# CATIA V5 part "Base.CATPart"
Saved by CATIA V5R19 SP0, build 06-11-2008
Part number: Base
Bounding box of the stored display mesh (mm): x -24 to 24, y 0 to 90, z 0 to 54
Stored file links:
  C:\Users\CADCIM\Desktop\CAT19\c13\Excercise-1\Part & Asm files\Base.CATPart
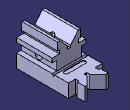
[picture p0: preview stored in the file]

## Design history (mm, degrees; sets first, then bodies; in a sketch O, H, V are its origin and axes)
Body1 (main body)
  Sketch1 on xy-plane, origin (0, 0, 0), H (1, 0, 0), V (0, 1, 0)
    line L1 (-24, 0) -> (24, 0)
    point P2 (24, 0)
    construction line L2 (-23.876, 50.8) -> (23.876, 50.8)
    point P3 (-23.876, 50.8)
    point P4 (23.876, 50.8)
    line L3 (24, 0) -> (24, 74)
    point P5 (24, 74)
    line L4 (24, 74) -> (14, 74)
    point P6 (14, 74)
    line L5 (14, 74) -> (14, 79)
    point P7 (14, 79)
    line L6 (14, 79) -> (16.5, 79)
    point P8 (16.5, 79)
    line L7 (16.5, 79) -> (16.5, 90)
    point P9 (16.5, 90)
    line L8 (16.5, 90) -> (13.5, 90)
    point P10 (13.5, 90)
    line L9 (13.5, 90) -> (2, 78.5)
    point P11 (2, 78.5)
    line L10 (2, 78.5) -> (2, 74)
    point P12 (2, 74)
    line L11 (2, 74) -> (0, 74)
    point P13 (0, 74)
    point P14 (0, 74)
    point P15 (-2, 74)
    line L12 (-2, 74) -> (0, 74)
    point P16 (-2, 78.5)
    line L13 (-2, 78.5) -> (-2, 74)
    point P17 (-13.5, 90)
    line L14 (-13.5, 90) -> (-2, 78.5)
    point P18 (-16.5, 90)
    line L15 (-16.5, 90) -> (-13.5, 90)
    point P19 (-16.5, 79)
    line L16 (-16.5, 79) -> (-16.5, 90)
    point P20 (-14, 79)
    line L17 (-14, 79) -> (-16.5, 79)
    point P21 (-14, 74)
    line L18 (-14, 74) -> (-14, 79)
    point P22 (-24, 74)
    line L19 (-24, 74) -> (-14, 74)
    point P23 (-23.876, 50.8)
    point P24 (23.876, 50.8)
    construction line L20 (23.876, 50.8) -> (-23.876, 50.8)
    point P25 (-24, 0)
    line L21 (-24, 0) -> (-24, 74)
    length L1 = 48
    distance P2 V = 24
    distance L13 L10 = 4
    distance L16 L7 = 33
    distance L5 L3 = 10
    length L18 = 5
    angle L14 L9 = 90
    distance L4 L8 = 16
    distance P17 P10 = 27
    distance L1 L8 = 90
    horizontal: L1 H, L2 H, L4 H, L6 H, L8 H, L11 H
    coincidence: H L1, P13 V, P13 P14, L12 L4
    vertical: L3 V, L5 V, L7 V, L10 V
    symmetry: P13 P14 V, P12 P15 V, L11 L12 V, P11 P16 V, L10 L13 V, P10 P17 V, L9 L14 V, P9 P18 V, L8 L15 V, P8 P19 V, L7 L16 V, P7 P20 V, L6 L17 V, P6 P21 V, L5 L18 V, P5 P22 V, L4 L19 V, P4 P23 V, P3 P24 V, L2 L20 V, P2 P25 V, L3 L21 V
  Pad1: profile Sketch1, direction (0, 0, 1), length 19
  Sketch2 on face of Pad1, origin (0, 0, 0), H (1, 0, 0), V (0, 0, 1)
    line L1 (17.5, 19) -> (17.5, 32)
    point P1 (17.5, 19)
    point P2 (17.5, 32)
    line L2 (17.5, 32) -> (24, 32)
    point P3 (24, 32)
    line L3 (24, 32) -> (24, 38)
    point P4 (24, 38)
    line L4 (24, 38) -> (13.5, 38)
    point P5 (13.5, 38)
    line L5 (13.5, 38) -> (13.5, 43)
    point P6 (13.5, 43)
    line L6 (13.5, 43) -> (16.5, 43)
    point P7 (16.5, 43)
    line L7 (16.5, 43) -> (16.5, 54)
    point P8 (16.5, 54)
    reference projected line E1 (24, 19) -> (-24, 19) from edge of Pad1
    reference projected line E2 (24, 0) -> (24, 19) from edge of Pad1
    line L8 (16.5, 54) -> (12.9083, 54)
    point P9 (12.9083, 54)
    point P10 (2, 41)
    line L9 (2, 41) -> (2, 38)
    point P11 (2, 38)
    line L10 (2, 38) -> (0, 38)
    point P12 (0, 38)
    line L11 (2, 41) -> (12.9083, 54)
    point P13 (-12.9083, 54)
    point P14 (-2, 41)
    line L12 (-2, 41) -> (-12.9083, 54)
    point P15 (0, 38)
    point P16 (-2, 38)
    line L13 (-2, 38) -> (0, 38)
    line L14 (-2, 41) -> (-2, 38)
    point P17 (-16.5, 54)
    line L15 (-16.5, 54) -> (-12.9083, 54)
    point P18 (-16.5, 43)
    line L16 (-16.5, 43) -> (-16.5, 54)
    point P19 (-13.5, 43)
    line L17 (-13.5, 43) -> (-16.5, 43)
    point P20 (-13.5, 38)
    line L18 (-13.5, 38) -> (-13.5, 43)
    point P21 (-24, 38)
    line L19 (-24, 38) -> (-13.5, 38)
    point P22 (-24, 32)
    line L20 (-24, 32) -> (-24, 38)
    point P23 (-17.5, 32)
    line L21 (-17.5, 32) -> (-24, 32)
    point P24 (-17.5, 19)
    line L22 (-17.5, 19) -> (-17.5, 32)
    line L23 (-17.5, 19) -> (17.5, 19)
    distance L2 H = 32
    distance L4 H = 38
    distance L6 H = 43
    distance L8 H = 54
    distance L9 V = 2
    length L9 = 3
    distance L22 L1 = 35
    distance L7 L16 = 33
    angle L12 L11 = 80
    distance L18 L5 = 27
    vertical: L1 V, L3 V, L5 V, L7 V, L9 V
    horizontal: L2 H, L4 H, L6 H, L8 H, L10 H, L23 H
    coincidence: P1 E1, L3 E2, P11 L4, P12 V, P12 P15
    symmetry: P9 P13 V, P10 P14 V, L11 L12 V, P12 P15 V, P11 P16 V, L10 L13 V, L9 L14 V, P8 P17 V, L8 L15 V, P7 P18 V, L7 L16 V, P6 P19 V, L6 L17 V, P5 P20 V, L5 L18 V, P4 P21 V, L4 L19 V, P3 P22 V, L3 L20 V, P2 P23 V, L2 L21 V, P1 P24 V, L1 L22 V
  Pad2: profile Sketch2, direction (0, 1, 0), length 50.8
  Sketch3 on face of Pad1, origin (4.0235, 27.8102, 0), H (1, 0, 0), V (0, -1, 0)
    point P1 (-4.0235, 2.8102)
    reference intersected line E1 through (-4.0235, 0) direction (0, 1) from yz-plane
    reference projected line E2 (-6.0235, 27.8102) -> (-16.9318, 27.8102) from edge [face of Pad2 from Sketch2.L12 | start face of Pad2]
    distance P1 E2 = 25
    coincidence: E1 P1
  Hole1: placed by Sketch3, at (0, 25, 0) direction (0, 0, 1), diameter 8, depth 54.102
  Sketch4 on face of Pad2, origin (17.5, 12.3932, 23.5222), H (0, 1, 0), V (0, 0, 1)
    point P1 (12.6068, 1.4778)
    reference projected line E1 (-12.3932, 8.4778) -> (-12.3932, -4.5222) from edge of Pad2
    reference projected line E2 (-12.3932, -23.5222) -> (61.6068, -23.5222) from edge of Pad1
    distance E1 P1 = 25
    distance E2 P1 = 25
  Hole2: placed by Sketch4, at (17.5, 25, 25) direction (-1, 0, 0), diameter 10, depth 54.102
  Sketch5 on face of Pad1, origin (0, 0, 19), H (1, 0, 0), V (0, 1, 0)
    construction line L1 (-24, 59) -> (24, 59)
    point P1 (-24, 59)
    point P2 (24, 59)
    construction line L2 (-12.5, 59) -> (12.5, 59)
    point P3 (-12.5, 59)
    point P4 (12.5, 59)
    line L3 (-12.5, 62) -> (12.5, 62)
    line L4 (12.5, 56) -> (-12.5, 56)
    arc A1 centre (12.5, 59) radius 3 from (12.5, 62) to (12.5, 56) cw
    arc A2 centre (-12.5, 59) radius 3 from (-12.5, 56) to (-12.5, 62) cw
    reference projected line E1 (24, 74) -> (24, 0) from edge of Pad1
    reference projected line E2 (-24, 74) -> (-24, 0) from edge of Pad1
    reference projected line E3 (24, 74) -> (14, 74) from edge [face of Pad1 from Sketch1.L4 | end face of Pad1]
    radius A1 = 3
    distance L2 E3 = 15
    length L2 = 25
    distance V P4 = 12.5
    horizontal: L1 H, L2 H
    coincidence: P3 L1, P2 E1, P1 E2
    tangency: A1 L3, A2 L3, A1 L4, A2 L4
    parallelism: L2 L3
  Pocket1: profile Sketch5, direction (0, 0, -1), length 1
  Sketch6 on face of Pad1, origin (24, 0, 0), H (0, 1, 0), V (0, 0, 1)
    point P1 (50.8, 19)
    line L1 (50.8, 19) -> (52.5321, 16)
    point P2 (52.5321, 16)
    line L2 (52.5321, 16) -> (54.2641, 19)
    line L3 (54.2641, 19) -> (50.8, 19)
    reference projected line E1 (74, 19) -> (0, 19) from edge of Pad1
    construction line L4 (52.5321, 16) -> (52.5321, 29.45)
    reference projected line E2 (50.8, 19) -> (50.8, 32) from edge [end face of Pad2 | face of Pad2 from Sketch2.L1]
    angle L1 L2 = 60
    distance P2 L3 = 3
    angle L4 L2 = 30
    horizontal: L3 H
    coincidence: L3 E1, P1 E2
    vertical: L4 V
  Pocket2: profile Sketch6, direction (-1, 0, 0), through (limit type 6)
